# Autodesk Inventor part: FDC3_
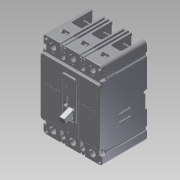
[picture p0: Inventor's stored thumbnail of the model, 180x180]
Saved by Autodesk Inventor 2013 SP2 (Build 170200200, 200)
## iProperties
Created: 2014-08
Part Number: FDC3_
Material: Generic
Document SubType Name: Modeling
Designer: DM/JS
Density: 1 g/cm^3
Description: TYPE FDC THERMAL MAGNETIC CIRCUIT BREAKERS THREE POLE, SERIES C
Translation Standard: STEP AP214IS
FileName: Y:\ECO-062745\WIP\New\FD3_.stp
PreProcessor: Autodesk Inventor 2012
PostProcessor: Build: 219, Release: 2012 SP2 - Date: Fri 04/27/2012
Sent Units: inch
Uncertainty: 0.00039370078740199997
MXEDIT: false
MXINVTNRV: INV Versioned Component|FDC3_|003.0
Author: DM/JS
Revision Number: 003
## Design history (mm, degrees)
node "FDC3_"
node "L1"
node "L2"
node "L3"
node "T1"
node "T2"
node "T3"
body "Solid1"
node "Base1"
